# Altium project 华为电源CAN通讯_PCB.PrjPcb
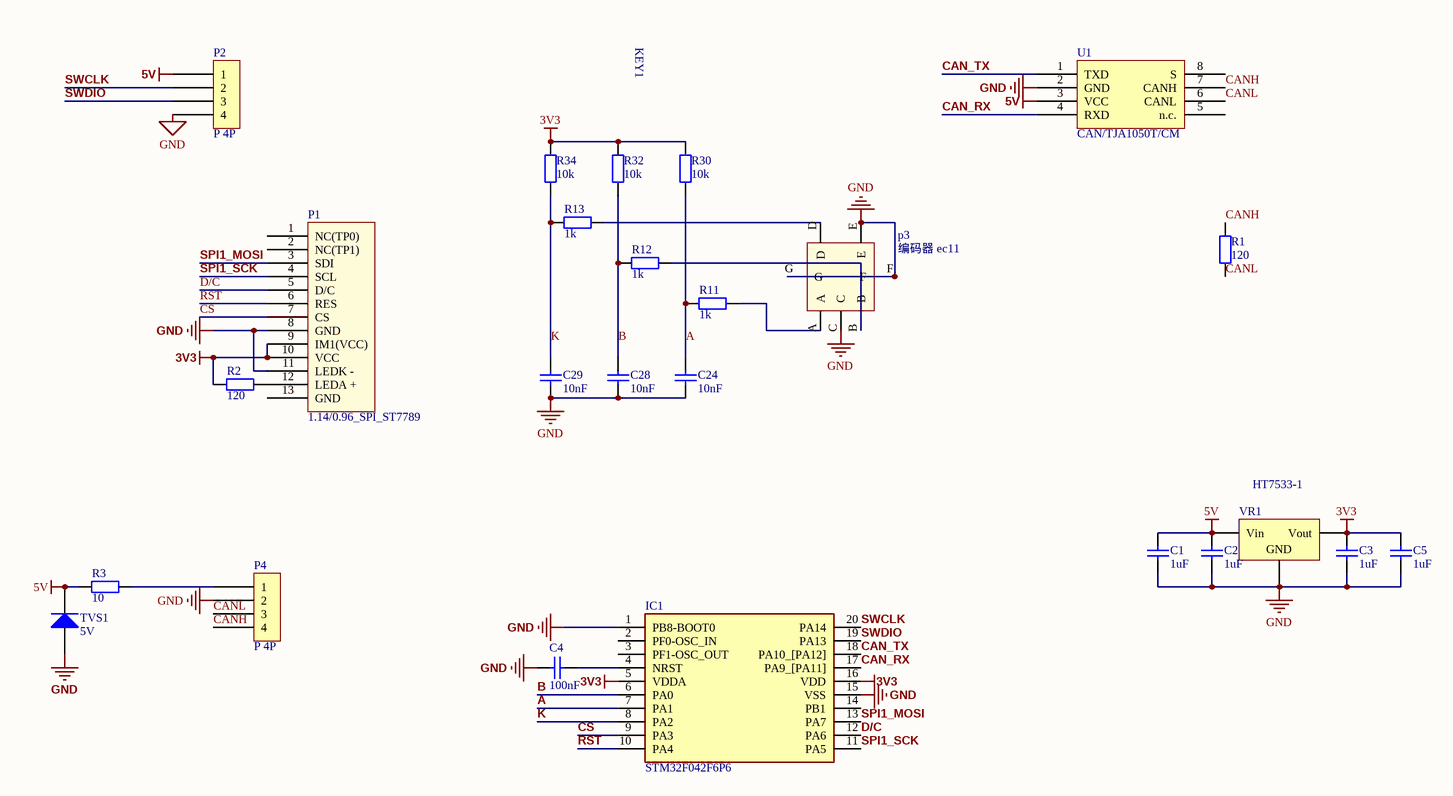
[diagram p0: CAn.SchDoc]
1 sheet, 25 parts. Net scope: global (net labels, ports and power ports of the same name join across sheets).
Board file: CAN.PcbDoc

## Sheet CAn.SchDoc
size A3; SheetNumber: 1; SheetTotal: 1

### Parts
C1  1uF  [C_0603]
C2  1uF  [C_0603]
C3  1uF  [C_0603]
C4  100nF  [C_0603]
C5  1uF  [C_0603]
C24  10nF  [C_0603]
C28  10nF  [C_0603]
C29  10nF  [C_0603]
IC1  STM32F042F6P6  [CLT34BT6]
P1  1.14/0.96_SPI_ST7789  [0.96_TFT_SPI_TOP]
P2  P 4P  [HDR1X4]
p3  编码器 ec11  [EC11]
P4  P 4P  [HDR1X4]
R1  120  [LC-0603_R]
R2  120  [R_0603]
R3  10  [R_0603]
R11  1k  [R_0603]
R12  1k  [R_0603]
R13  1k  [R_0603]
R30  10k  [R_0603]
R32  10k  [R_0603]
R34  10k  [R_0603]
TVS1  5V  [SOD123]
U1  CAN/TJA1050T/CM  [LC-SOIC-8_150mil]
VR1  HT7533-1  [LC-SOT-89(SOT-89-3)]

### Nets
3V3: C3.2 C5.2 IC1.5(VDDA) IC1.16(VDD) P1.9(IM1(VCC)) P1.10(VCC) R2.1 R30.1 R32.1 R34.1 VR1.3(Vout)
5V: C1.2 C2.2 P2.1 R3.1 TVS1.K U1.3(VCC) VR1.2(Vin)
GND: C1.1 C2.1 C3.1 C4.1 C5.1 C24.2 C28.2 C29.2 IC1.1(PB8-BOOT0) IC1.15(VSS) P1.8(GND) P1.11(LEDK_-) P2.4 p3.C p3.E p3.F p3.G P4.2 TVS1.A U1.2(GND) VR1.1(GND)
A: C24.1 IC1.7(PA1) R11.1 R30.2
B: C28.1 IC1.6(PA0) R12.1 R32.2
CAN_RX: IC1.17(PA9_[PA11]) U1.4(RXD)
CAN_TX: IC1.18(PA10_[PA12]) U1.1(TXD)
CANH: P4.4 R1.2 U1.7(CANH)
CANL: P4.3 R1.1 U1.6(CANL)
CS: IC1.9(PA3) P1.7(CS)
D/C: IC1.12(PA6) P1.5(D/C)
K: C29.1 IC1.8(PA2) R13.1 R34.2
RST: IC1.10(PA4) P1.6(RES)
SPI1_MOSI: IC1.13(PA7) P1.3(SDI)
SPI1_SCK: IC1.11(PA5) P1.4(SCL)
SWCLK: IC1.20(PA14) P2.2
SWDIO: IC1.19(PA13) P2.3
NetC4_2: C4.2 IC1.4(NRST)
NetP1_12: P1.12(LEDA_+) R2.2
Netp3_A: p3.A R11.2
Netp3_B: p3.B R12.2
Netp3_D: p3.D R13.2
NetP4_1: P4.1 R3.2

Not connected (* = marked no-connect by the designer): IC1 2(PF0-OSC_IN) 3(PF1-OSC_OUT) 14(PB1); P1 1(NC(TP0)) 2(NC(TP1)) 13(GND); U1 5(n.c.) 8(S)

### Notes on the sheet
- KEY1

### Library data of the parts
C1-C5 C24 C28 C29 = 贴片电容_
IC1 = STM32F042F6P6: Integrated Circuit; Manufacturer_Name: STMicroelectronics
R1 = 0603 10KΩ (1002) 1%: 贴片电阻
R2 R3 R11-R13 R30 R32 R34 = 贴片电阻
TVS1 = SOD: 二极管
U1 = CAN/TJA1050T/CM: CAN
VR1 = SOT-89 HT7533-1: 低压差线性稳压(LDO)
